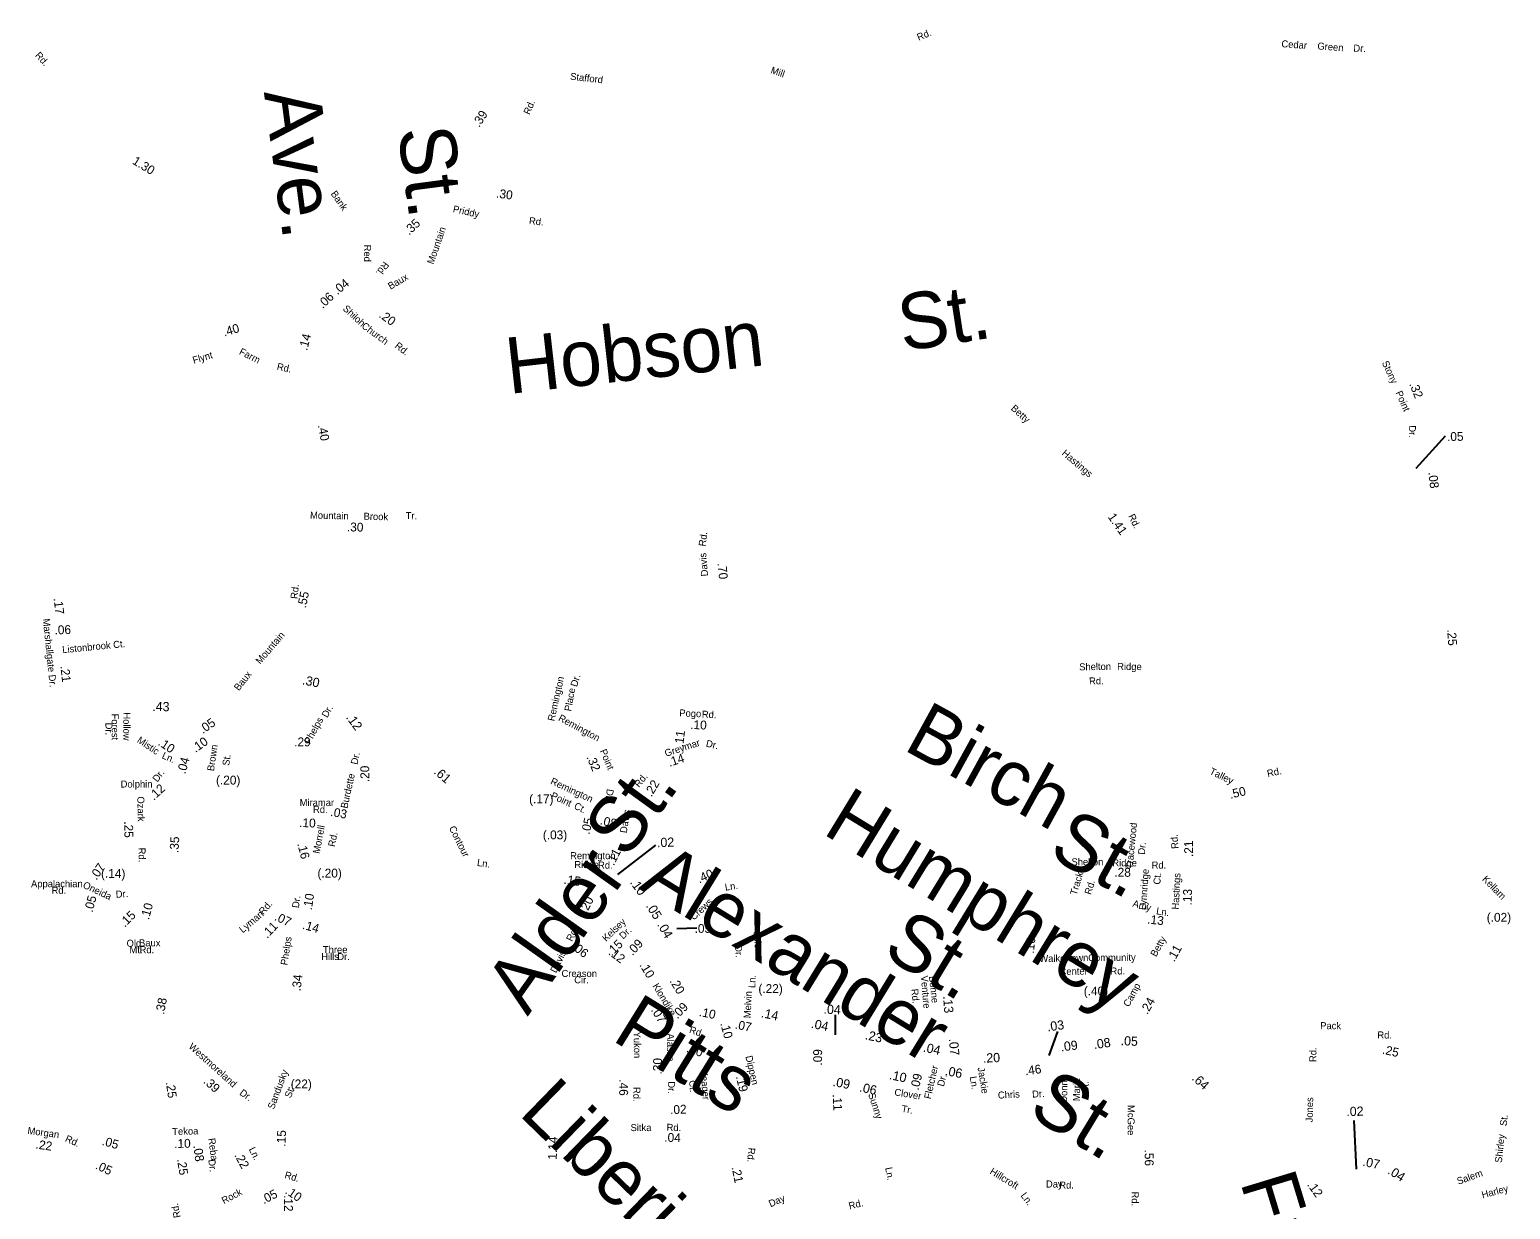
# Model space of a CAD drawing. Extents: x 1553981 to 1780076, y 812965 to 996873.
# Drawn here: x 1634131 to 1636637, y 851594 to 853590 of the extents above; entities that cross this region are included whole.
import ezdxf

# ---------------------------------------------------------------- set-up
doc = ezdxf.new("R2010")
doc.units = 0
for name, color, linetype in [('Exist Road Non-System Type 51 Label', 7, 'Continuous'), ('Exist Road Primary NC Service Mileage Hundredths English Label', 7, 'Continuous'), ('Exist Road Secondary Mileage Hundredths English Label', 7, 'Continuous'), ('Map Preparation Border Antique Large Shape', 7, 'Continuous')]:
    doc.layers.add(name, color=color, linetype=linetype)

msp = doc.modelspace()

# ---------------------------------------------------------------- linework, layer by layer
at = {"layer": 'Exist Road Primary NC Service Mileage Hundredths English Label'}
for p, q in [((1635126.3, 852160.8), (1635190.3, 852210.6)), ((1635494.7, 851889.5), (1635494.7, 851923.6)), ((1635856.3, 851854.6), (1635871, 851895)), ((1636376.5, 851662.2), (1636372.3, 851744.5))]:
    msp.add_line(p, q, dxfattribs=at)
at = {"layer": 'Exist Road Secondary Mileage Hundredths English Label'}
for p, q in [((1636477.2, 852848.3), (1636527, 852902.8)), ((1635225.9, 852069.3), (1635260, 852070.9))]:
    msp.add_line(p, q, dxfattribs=at)

# ---------------------------------------------------------------- texts
at = {"layer": 'Exist Road Non-System Type 51 Label'}
for s, height, rotation, p in [('Cedar', 11.88, 355.8987, (1636248.9, 853560.6)), ('Green', 11.88, 355.8987, (1636309.8, 853556.8)), ('Dr.', 11.87, 358.1095, (1636370.9, 853553.1)), ('Ave.', 95, 277.4883, (1634527, 853484.5)), ('St.', 95, 277.4896, (1634753.6, 853421.3)), ('St.', 95, 8.7473, (1635608.3, 853045.8)), ('Hobson', 95, 6.4158, (1634941.8, 852973.7)), ('Dr.', 11.88, 72.3257, (1635056.8, 852477.4)), ('Shelton', 11.88, 0.9183, (1635907, 852506.2)), ('Ridge', 11.88, 359.6758, (1635971.2, 852506.9)), ('Remington', 11.88, 77.3478, (1635018.6, 852419.5)), ('Place', 11.88, 79.7967, (1635047.1, 852436.2)), ('Rd.', 11.88, 0.9183, (1635923.8, 852482.3)), ('Birch', 95, 331.2052, (1635607.2, 852373.1)), ('Forest', 11.88, 270.2143, (1634269.4, 852433.1)), ('Hollow', 11.88, 270.2143, (1634289.1, 852435.1)), ('Dr.', 11.88, 270.2143, (1634258.9, 852417.7)), ('St.', 95, 54.0301, (1635140.6, 852184.9)), ('Humphrey', 95, 328.5927, (1635470.6, 852231.1)), ('St.', 95, 331.2052, (1635852.3, 852192.7)), ('Tracewood', 11.88, 84.2935, (1635997.2, 852169.8)), ('Contour', 11.88, 296.5012, (1634839.9, 852239.5)), ('Alder', 95, 54.6584, (1634973.4, 851920)), ('Alexander', 95, 328.5097, (1635160, 852137.7)), ('Dr.', 11.88, 84.2935, (1636017.9, 852194)), ('Ln.', 11.88, 351.3159, (1634887.2, 852175.5)), ('Lynnridge', 11.88, 86.0118, (1636020.2, 852100.4)), ('Track', 11.88, 73.2286, (1635902.6, 852125)), ('Rd.', 11.88, 73.2286, (1635926.9, 852125.9)), ('Ct.', 11.88, 86.0118, (1636044.2, 852143.5)), ('Kellam', 11.88, 314.1224, (1636588.2, 852152)), ('St.', 95, 328.7902, (1635571.5, 852025.2)), ('Pitts', 95, 328.2355, (1635114, 851881.6)), ('Rd.', 11.87, 89.7053, (1636308.4, 851843.6)), ('Yeager', 11.87, 274.5695, (1635266.1, 851830.1)), ('Ln.', 11.87, 279.3537, (1635721.6, 851818.6)), ('Jackie', 11.87, 279.3537, (1635735, 851833.8)), ('St.', 95, 328.7751, (1635817.8, 851755)), ('Donna', 11.87, 89.1455, (1635886.5, 851774.7)), ('Liberia', 95, 315.8274, (1634956.6, 851755.6)), ('Ct.', 11.88, 274.2924, (1635246.7, 851812.3)), ('Clover', 11.87, 350.5549, (1635593.5, 851787.3)), ('Chris', 11.88, 3.4281, (1635769.7, 851781.5)), ('Dr.', 11.88, 3.4281, (1635827.6, 851783.3)), ('Marie', 11.87, 89.1455, (1635908.1, 851777.2)), ('Ct.', 11.87, 89.1455, (1635922.6, 851790.6)), ('Sunny', 11.88, 288.1886, (1635549.6, 851789)), ('Tr.', 11.87, 350.5549, (1635605.6, 851759.1)), ('Jones', 11.88, 88.7142, (1636302.1, 851741.4)), ('St.', 11.88, 83.9484, (1636630.5, 851734.8)), ('Shirley', 11.88, 83.9484, (1636622.2, 851672.6)), ('Ln.', 11.88, 280.8547, (1635578.5, 851664.5)), ('Hillcroft', 11.88, 328.4785, (1635754.6, 851655.4)), ('Free', 95, 286.9422, (1636179.1, 851640.9)), ('Salem', 11.88, 19.6432, (1636548.7, 851635.9)), ('Ln.', 11.88, 305.7319, (1635807.2, 851617.7)), ('Harley', 11.88, 14.981, (1636589.8, 851612.8))]:
    msp.add_text(s, height=height, rotation=rotation, dxfattribs=at).set_placement(p)
at = {"layer": 'Exist Road Primary NC Service Mileage Hundredths English Label'}
for s, rotation, p in [('.30', 348.6901, (1634591.1, 852482.7)), ('.43', 358.7982, (1634338.2, 852437.6)), ('.12', 306.076, (1634665.3, 852426.4)), ('.61', 319.3124, (1634813.4, 852332.8)), ('.02', 1.9025, (1635192.7, 852207)), ('.15', 351.3323, (1635033.7, 852145.4)), ('.10', 305.3509, (1635145.9, 852147.3)), ('.05', 301.722, (1635173.1, 852107.8)), ('.04', 300.3454, (1635192.1, 852076)), ('.14', 347.9262, (1635367.7, 851919.7)), ('.04', 357.3362, (1635474, 851925.5)), ('.04', 347.6474, (1635452.3, 851901.8)), ('.23', 348.2559, (1635543.6, 851882.2)), ('.03', 8.0702, (1635853.6, 851895.3)), ('.04', 347.5172, (1635641.9, 851861.5)), ('.09', 7.0649, (1635876.4, 851861.4)), ('.08', 7.941, (1635932.3, 851865.4)), ('.05', 357.2073, (1635976.9, 851872.2)), ('.20', 2.3215, (1635744.3, 851842.4)), ('.06', 349.104, (1635679, 851821.6)), ('.64', 317.7792, (1636096.5, 851814.7)), ('.02', 1.5363, (1636359.3, 851752)), ('.07', 348.0957, (1636385.7, 851668.2)), ('.04', 327.8477, (1636427.8, 851655.8))]:
    msp.add_text(s, height=15.62, rotation=rotation, dxfattribs=at).set_placement(p)
at = {"layer": 'Exist Road Secondary Mileage Hundredths English Label'}
for s, height, rotation, p in [('.39', 15, 56.6278, (1634891.4, 853424)), ('1.30', 15, 328.5971, (1634303.2, 853364.2)), ('.30', 15, 352.6313, (1634919.5, 853306.2)), ('.35', 15, 43.1942, (1634772.8, 853241.7)), ('.04', 15, 39.1983, (1634651.4, 853140.9)), ('.06', 15, 43.4199, (1634626.6, 853117.4)), ('.20', 15, 324.1364, (1634720.6, 853104.7)), ('.40', 15, 16.4036, (1634460.2, 853071)), ('.14', 15, 74.8187, (1634600.1, 853046.5)), ('.32', 15, 292.0317, (1636465.3, 852990.6)), ('.40', 15, 281.1305, (1634618.2, 852920.7)), ('.05', 15, 1.2413, (1636529.7, 852894.1)), ('.08', 15, 276.5366, (1636497.9, 852841.1)), ('1.41', 15, 304.975, (1635954.7, 852765.8)), ('.30', 15, 358.6052, (1634667.5, 852741.5)), ('.70', 15, 275.4094, (1635294.9, 852687.5)), ('.17', 15, 276.5201, (1634171.2, 852628)), ('.55', 15, 78.5044, (1634598.1, 852610.8)), ('.06', 15, 2.0377, (1634173, 852566.9)), ('.25', 15, 274.3125, (1636529.6, 852575.3)), ('.21', 15, 276.5201, (1634182.6, 852513.2)), ('.05', 15, 35.2111, (1634423.9, 852398.3)), ('.10', 15, 357.6171, (1635248.4, 852407.2)), ('.11', 15, 82.6369, (1635236.4, 852376)), ('.10', 15, 326.2049, (1634346.7, 852380.8)), ('.10', 15, 35.5502, (1634411.4, 852366.4)), ('.29', 15, 359.5068, (1634578.3, 852377.8)), ('.04', 15, 74.8332, (1634394.2, 852329.9)), ('.32', 15, 292.8671, (1635072.8, 852359.5)), ('.14', 15, 18.1709, (1635213.6, 852343)), ('(.20)', 15, 359.6505, (1634446, 852313.2)), ('.20', 15, 90, (1634705.3, 852317.1)), ('.22', 15, 59.4354, (1635183.2, 852291.2)), ('.12', 15, 42.7342, (1634340.8, 852285.6)), ('(.17)', 15, 0.0963, (1634976, 852281.2)), ('.50', 15, 13.5291, (1636163.1, 852288.9)), ('.03', 15, 349.8194, (1634638.8, 852260.1)), ('.25', 15, 271.2817, (1634290.5, 852250.7)), ('.10', 15, 357.5082, (1634586.6, 852241.4)), ('.05', 15, 76.8886, (1635078.1, 852227.9)), ('.08', 15, 346.3719, (1635095.1, 852245.8)), ('.35', 15, 86.7635, (1634382.4, 852196.9)), ('.16', 15, 284.3694, (1634583.6, 852212.8)), ('.11', 15, 62.8648, (1635119.1, 852174.9)), ('.21', 15, 90.8403, (1636099.9, 852190.5)), ('.07', 15, 55.6835, (1634243.6, 852150.3)), ('(.14)', 15, 359.516, (1634251.4, 852155.3)), ('(.20)', 15, 359.8558, (1634617.7, 852155.8)), ('.40', 15, 23.6113, (1635263.9, 852145.7)), ('.28', 15, 359.2195, (1635966.4, 852157.3)), ('.05', 15, 75.0969, (1634237, 852096)), ('.10', 15, 81.2907, (1634608.1, 852100)), ('.20', 15, 62.7957, (1635073.1, 852093.9)), ('.13', 15, 88.0205, (1636097.1, 852108.4)), ('.15', 15, 44.4081, (1634291.5, 852070.9)), ('.10', 15, 74.4206, (1634332.3, 852083.4)), ('.07', 15, 335.1936, (1634543.8, 852084.3)), ('.11', 15, 46.4217, (1634532.8, 852052)), ('.14', 15, 344.0314, (1634591.3, 852069.3)), ('.05', 15, 0.3267, (1635256.1, 852062.1)), ('.13', 15, 353.7653, (1636021.6, 852078)), ('.15', 15, 43.7786, (1635115.8, 852022)), ('.09', 15, 46.2957, (1635150.9, 852022.7)), ('.10', 15, 84.6474, (1635830.3, 852026.6)), ('.06', 15, 323.0138, (1635046.9, 852035.7)), ('.12', 15, 322.9133, (1635109, 852026.5)), ('.11', 15, 60.8474, (1636067.7, 852012.1)), ('.10', 15, 301.1457, (1635162.1, 852007.7)), ('.34', 15, 83.5724, (1634589.2, 851963.1)), ('.20', 15, 300.8578, (1635213.2, 851980.7)), ('(.22)', 15, 0.0071, (1635364, 851960.3)), ('(.40)', 15, 359.9506, (1635914.7, 851956.3)), ('.38', 15, 79.2891, (1634358, 851923.4)), ('.09', 15, 45.7431, (1635226.9, 851915.6)), ('.13', 15.62, 274.6975, (1635676.5, 851954.7)), ('.24', 15, 60.4615, (1636022.4, 851923)), ('.07', 15, 301.8499, (1635181.6, 851931.6)), ('.10', 15, 348.494, (1635262.7, 851921.7)), ('.10', 15, 285.5368, (1635299.3, 851908.8)), ('.07', 15, 348.6482, (1635323.5, 851900.3)), ('.20', 15, 341.0599, (1635240.9, 851861)), ('.07', 15.62, 274.6975, (1635686.4, 851882.9)), ('.25', 15, 347.5235, (1636419, 851857.9)), ('.30', 15, 89.054, (1635200.5, 851822.4)), ('.09', 15, 89.7057, (1635471.7, 851837.5)), ('.10', 15.62, 347.5805, (1635584.5, 851814.9)), ('.09', 15, 76.3211, (1635635, 851795)), ('.46', 15, 8.1351, (1635816.1, 851821)), ('.25', 15, 278.6049, (1634361, 851809.2)), ('.39', 15, 318.0013, (1634423.6, 851809.1)), ('.(22)', 15, 359.6071, (1634566.9, 851799.2)), ('.46', 15, 269.9778, (1635128.5, 851814.4)), ('.19', 15, 283.6649, (1635325.7, 851818.9)), ('.09', 15.62, 349.14, (1635489, 851803.2)), ('.06', 15.62, 347.5805, (1635534, 851794)), ('.02', 15, 2.3902, (1635214.9, 851755.3)), ('.11', 15, 272.3534, (1635489.8, 851788.9)), ('.15', 15, 87.4379, (1634563.5, 851700.2)), ('.04', 15, 358.3467, (1635204.6, 851708.8)), ('.22', 15, 352.1529, (1634140.1, 851697.3)), ('.05', 15, 344.2479, (1634252, 851703.6)), ('.10', 15, 0.6199, (1634375.4, 851698.3)), ('.08', 15, 277.7185, (1634407.6, 851702)), ('1.14', 15, 88.5437, (1635022.7, 851678.2)), ('.56', 15, 270.1978, (1636017.9, 851695.5)), ('.05', 15, 335.1638, (1634240.7, 851663.5)), ('.25', 15, 278.781, (1634380, 851678.9)), ('.22', 15, 298.4308, (1634476.6, 851686)), ('.21', 15, 281.4829, (1635318.6, 851665.3)), ('.05', 15, 27.5342, (1634527, 851602.8)), ('.10', 15, 325.5816, (1634561.8, 851622.2)), ('.12', 15, 305.4537, (1636292.1, 851635.8)), ('.12', 15, 271.0461, (1634560.9, 851618.3))]:
    msp.add_text(s, height=height, rotation=rotation, dxfattribs=at).set_placement(p)
for s, p in [('(.03)', (1634999.2, 852220.4)), ('(.02)', (1636596.7, 852080.9))]:
    msp.add_text(s, height=15, dxfattribs=at).set_placement(p)
at = {"layer": 'Map Preparation Border Antique Large Shape'}
for s, height, rotation, p in [('Rd.', 11.88, 22.5439, (1635635.3, 853571.3)), ('Rd.', 11.88, 311.7635, (1634139.1, 853546.1)), ('Mill', 11.87, 340.8661, (1635383.8, 853516.9)), ('Stafford', 11.88, 353.4697, (1635045, 853505.6)), ('Rd.', 11.88, 66.5073, (1634976.7, 853445.4)), ('Bank', 11.87, 304.8675, (1634639.6, 853312.5)), ('Priddy', 11.88, 347.8014, (1634846.2, 853281.5)), ('Rd.', 11.88, 353.4787, (1634975.3, 853261.4)), ('Mountain', 11.88, 71.0693, (1634814.1, 853192.3)), ('Red', 11.88, 269.9097, (1634696.5, 853226.5)), ('Rd.', 11.88, 233.4396, (1634730.4, 853198.9)), ('Baux', 11.88, 30.3983, (1634741.4, 853150)), ('Shiloh', 11.88, 317.0012, (1634659.7, 853116.9)), ('Church', 11.88, 323.5062, (1634691.3, 853086.6)), ('Farm', 11.88, 332.9724, (1634484.1, 853041.7)), ('Rd.', 11.88, 322.0189, (1634747.6, 853053.3)), ('Flynt', 11.87, 16.4037, (1634408.4, 853024.9)), ('Rd.', 11.88, 348.1132, (1634548.3, 853014.9)), ('Stony', 11.88, 295.1942, (1636418.9, 853026.7)), ('Point', 11.88, 293.7157, (1636442.1, 852976.1)), ('Betty', 11.87, 317.6173, (1635790.4, 852948.2)), ('Dr.', 11.88, 270.9343, (1636464.9, 852920.6)), ('Hastings', 11.88, 319.635, (1635876.5, 852871.9)), ('Mountain', 11.88, 358.9005, (1634605.1, 852762.9)), ('Brook', 11.88, 358.6052, (1634695.7, 852761.1)), ('Tr.', 11.88, 358.6052, (1634766.9, 852762.2)), ('Rd.', 11.88, 295.9661, (1635989.6, 852767.3)), ('Rd.', 11.87, 82.4143, (1635274.4, 852715.4)), ('Davis', 11.88, 95.1193, (1635279, 852665.8)), ('Rd.', 11.88, 83.8137, (1634583.8, 852626.6)), ('Marshallgate Dr.', 11.875, 275.909, (1634152.8, 852593.2)), ('Listonbrook Ct.', 11.875, 5.57, (1634186.4, 852535.3)), ('Mountain', 11.88, 49.3436, (1634520.8, 852515.7)), ('Baux', 11.88, 51.5526, (1634484.6, 852470.7)), ('Phelps', 11.88, 60.7452, (1634604.6, 852380.4)), ('Dr.', 11.88, 60.7452, (1634634.3, 852425.1)), ('Remington', 11.88, 331.6691, (1635024.3, 852422)), ('Pogo', 11.88, 357.6171, (1635230, 852428.4)), ('Rd.', 11.88, 357.6171, (1635268.1, 852426.2)), ('Mistic', 11.88, 326.2049, (1634311.3, 852385.3)), ('Brown', 11.88, 81.9149, (1634442.6, 852335.2)), ('Point', 11.88, 292.9471, (1635095.4, 852370)), ('Greymar', 11.87, 18.1709, (1635207.6, 852359.9)), ('Dr.', 11.87, 346.7736, (1635274.4, 852377.4)), ('Ln.', 11.88, 336.0433, (1634353.4, 852358)), ('St.', 11.88, 81.9149, (1634468.3, 852344.3)), ('Dr.', 11.88, 77.6456, (1634685.4, 852346)), ('Dr.', 11.88, 53.1471, (1634346.9, 852316.2)), ('Burdette', 11.88, 77.6456, (1634668.3, 852271.7)), ('Remington', 11.88, 335.2771, (1635011, 852314.5)), ('Rd.', 11.88, 51.0901, (1635162, 852307.2)), ('Talley', 11.88, 334.344, (1636126.4, 852331.5)), ('Rd.', 11.88, 12.1869, (1636226.2, 852325.7)), ('Point', 11.88, 335.8237, (1635011.7, 852290.1)), ('Dr.', 11.88, 260.4127, (1635107.8, 852306.3)), ('Ozark', 11.88, 271.2817, (1634312.8, 852292.8)), ('Ct.', 11.88, 333.0775, (1635050.8, 852273.1)), ('Davis', 11.88, 81.0836, (1635141.2, 852230.3)), ('Morrell', 11.88, 79.1788, (1634621.2, 852195.4)), ('Rd.', 11.88, 79.1788, (1634647.2, 852207)), ('Rd.', 11.87, 94.3558, (1636075.2, 852204.6)), ('Rd.', 11.88, 271.3739, (1634314.8, 852206.1)), ('Remington', 11.88, 0.0005, (1635045.4, 852186.8)), ('Ridge', 11.87, 359.9866, (1635052.6, 852171.7)), ('Rd.', 11.88, 359.8351, (1635092.6, 852170.8)), ('Oneida', 11.88, 334.928, (1634219.5, 852139)), ('Ln.', 11.88, 8.8428, (1635308.2, 852133.4)), ('Hastings', 11.88, 87.1643, (1636075.4, 852101.3)), ('Dr.', 11.88, 4.4962, (1634276.8, 852121.3)), ('Dr.', 11.87, 81.9301, (1634586.2, 852103.5)), ('Lyman', 11.88, 40.2592, (1634491.3, 852061.1)), ('Rd.', 11.88, 49.3127, (1634526.3, 852091.8)), ('Crews', 11.88, 43.0866, (1635254.9, 852082.6)), ('Amy', 11.87, 345.1968, (1635996.5, 852106.8)), ('Ln.', 11.88, 351.0609, (1636036.7, 852093.7)), ('Rd.', 11.88, 62.7957, (1635048.6, 852046.5)), ('Kelsey', 11.88, 43.7786, (1635106.4, 852046.5)), ('Phelps', 11.88, 81.1724, (1634566.8, 852006.7)), ('Dr.', 11.88, 43.7786, (1635135.2, 852050.6)), ('Jolene', 11.88, 274.5609, (1635355.7, 852063.9)), ('Betty', 11.87, 60.8474, (1636037.1, 852020.6)), ('Davis', 11.88, 64.0107, (1635021.7, 851993.2)), ('Dr.', 11.88, 274.5609, (1635324.1, 852040.8)), ('Walkertown', 11.87, 1.3027, (1635839.6, 852012.5)), ('Community', 11.88, 0.5306, (1635922.3, 852014.1)), ('Creason', 11.87, 359.6686, (1635030.8, 851987.6)), ('Center', 11.87, 1.3027, (1635873.9, 851990.6)), ('Rd.', 11.88, 0.5306, (1635959.9, 851991.6)), ('Cir.', 11.88, 359.4749, (1635052.3, 851976.8)), ('Klondike', 11.88, 301.1457, (1635184.3, 851972.3)), ('Ln.', 11.88, 87.2937, (1635358.6, 851968.6)), ('Venture', 11.88, 274.8431, (1635638.9, 851989.2)), ('Bonne', 11.87, 276.243, (1635652.6, 851988.5)), ('Camp', 11.88, 61.396, (1635991.1, 851935.8)), ('Melvin', 11.88, 87.2937, (1635350.9, 851917.5)), ('Rd.', 11.88, 275.8535, (1635622.5, 851966.9)), ('Yukon', 11.87, 270.4223, (1635153, 851895)), ('Rd.', 11.88, 341.0599, (1635246, 851893.4)), ('Pack', 11.88, 359.6279, (1636314.8, 851899.2)), ('Rd.', 11.88, 359.6279, (1636411.6, 851883.5)), ('Westmoreland', 11.875, 318.0013, (1634398.7, 851868.2)), ('Alaska', 11.88, 270.5882, (1635209.2, 851892)), ('Dippen', 11.88, 283.2312, (1635341.9, 851853)), ('Sandusky', 11.87, 69.7034, (1634544.1, 851762.7)), ('Fletcher', 11.87, 77.1541, (1635655.7, 851780.2)), ('Dr.', 11.88, 75.7395, (1635677.8, 851801.3)), ('Dr.', 11.88, 324.0101, (1634484.7, 851789.1)), ('St.', 11.88, 69.4187, (1634572.7, 851781.8)), ('Rd.', 11.88, 270.4572, (1635152.2, 851801.3)), ('Dr.', 11.88, 270.7508, (1635210.9, 851810.8)), ('McGee', 11.88, 270, (1635988.9, 851770.8)), ('Morgan', 11.87, 352.1529, (1634126.5, 851722.1)), ('Rd.', 11.88, 336.6263, (1634189.6, 851709.6)), ('Tekoa', 11.88, 1.7745, (1634372.2, 851719.9)), ('Sitka', 11.88, 0.1303, (1635147.7, 851726.7)), ('Rd.', 11.88, 358.3467, (1635208.5, 851727.3)), ('Reba', 11.88, 277.7185, (1634432.8, 851714.1)), ('Ln.', 11.87, 295.8822, (1634501.3, 851696.2)), ('Rd.', 11.88, 264.7953, (1635347.1, 851699.1)), ('Dr.', 11.88, 277.7185, (1634432.9, 851678.1)), ('Rd.', 11.88, 343.6416, (1634561.2, 851647.6)), ('Rock', 11.88, 27.8218, (1634459.4, 851603)), ('Rd.', 11.88, 270, (1635995.7, 851624.5)), ('Rd.', 11.88, 101.3696, (1634386.4, 851581.2)), ('Day', 11.88, 23.7559, (1635384.6, 851597.7)), ('Rd.', 11.88, 13.5854, (1635518.4, 851594.1))]:
    msp.add_text(s, height=height, rotation=rotation, dxfattribs=at).set_placement(p)
for s, height, p in [('Dolphin', 11.88, (1634284.7, 852308)), ('Miramar', 11.88, (1634587.6, 852276.6)), ('Rd.', 11.88, (1634610.3, 852265)), ('Shelton', 11.88, (1635893.9, 852176.4)), ('Ridge', 11.88, (1635963.1, 852174.6)), ('Rd.', 11.88, (1636029.5, 852170.9)), ('Appalachian', 11.875, (1634133, 852139.3)), ('Rd.', 11.88, (1634167.7, 852128.2)), ('Old', 11.88, (1634294.7, 852038.6)), ('Baux', 11.88, (1634315.8, 852039.2)), ('Mt.', 11.88, (1634299.6, 852027.7)), ('Rd.', 11.88, (1634316.7, 852027.7)), ('Hills', 11.88, (1634624.1, 852016.1)), ('Three', 11.88, (1634627, 852027.8)), ('Dr.', 11.88, (1634651.3, 852016)), ('Day', 11.88, (1635850.7, 851631.3)), ('Rd.', 11.88, (1635873.3, 851629.5))]:
    msp.add_text(s, height=height, dxfattribs=at).set_placement(p)

doc.saveas('drawing.dxf')
